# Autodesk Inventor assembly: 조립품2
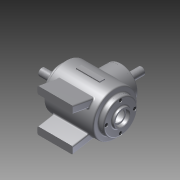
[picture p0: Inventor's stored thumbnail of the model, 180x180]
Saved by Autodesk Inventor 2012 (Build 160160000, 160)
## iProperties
Created: 2015-01
Part Number: 조립품2
Document SubType Name: Assembly
Designer: Class3-User
Author: Class3-User
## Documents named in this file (12)
- C:\Users\Class3-User\Desktop\450106V1001.iam
- C:\Users\Class3-User\Desktop\본체.ipt
- C:\Users\Class3-User\Downloads\450106V1001\M4.ipt
- C:\Users\Class3-User\Downloads\450106V1001\메인 베벨기어.ipt
- C:\Users\Class3-User\Downloads\450106V1001\메인 축.ipt
- C:\Users\Class3-User\Downloads\450106V1001\베어링 6203.ipt
- C:\Users\Class3-User\Downloads\450106V1001\서브 베벨기어.ipt
- C:\Users\Class3-User\Downloads\450106V1001\서브 축.ipt
- C:\Users\Class3-User\Downloads\450106V1001\오일실.ipt
- C:\Users\Class3-User\Downloads\450106V1001\커버.ipt
- C:\Users\Class3-User\Downloads\450106V1001\키 4x4.ipt
- C:\Users\Class3-User\Downloads\450106V1001\키 5x5.ipt
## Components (12 placed, 1 different names)
1. M4:6
2. M4:7
3. M4:8
4. M4:9
5. M4:1
6. M4:10
7. M4:11
8. M4:12
9. M4:13
10. M4:14
11. M4:15
12. M4:16
